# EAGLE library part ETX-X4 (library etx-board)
IDE 1, IDE 2, Ethernet, Miscellaneous ETX Board Connector 100 Pos. Source: www.kontron.com/techlib/whitepapers/etx_spec.pdf
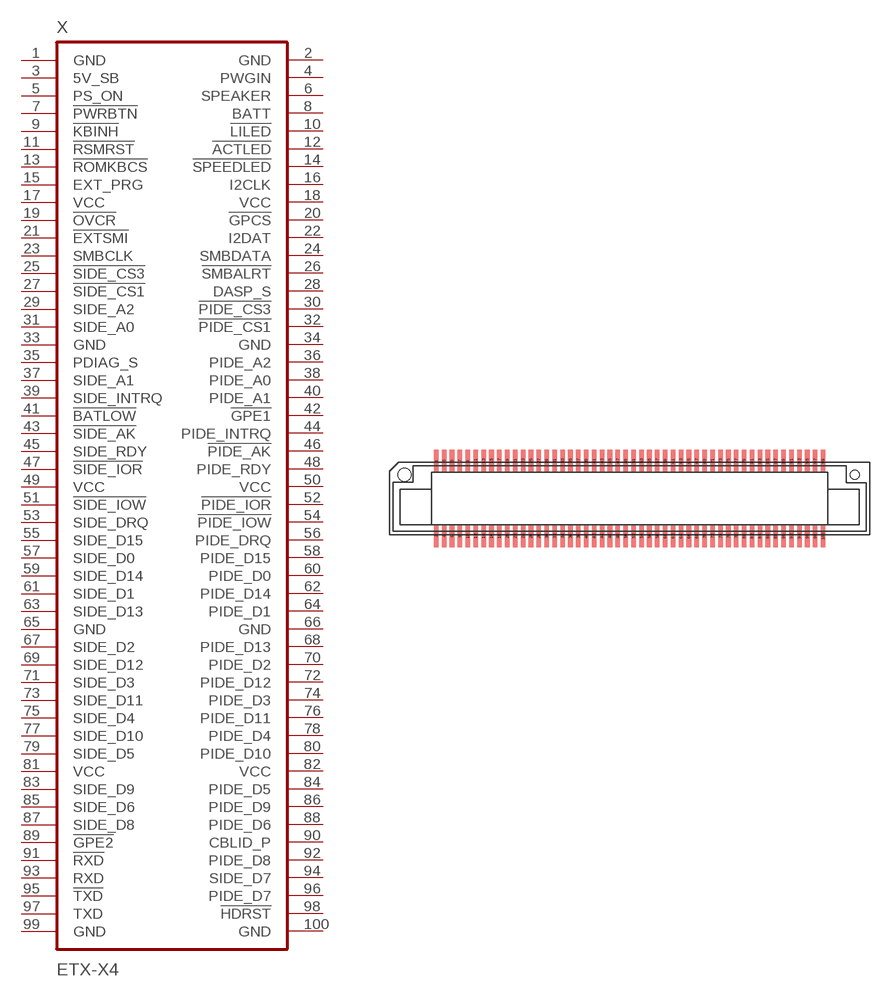
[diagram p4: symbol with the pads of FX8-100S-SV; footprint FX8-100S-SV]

Designator prefix X

## ETX-X4  [FX8-100S-SV]
1  GND  pwr
2  GND  pwr
3  5V_SB
4  PWGIN
5  PS_ON
6  SPEAKER
7  !PWRBTN
8  BATT
9  !KBINH
10  !LILED
11  !RSMRST
12  !ACTLED
13  !ROMKBCS
14  !SPEEDLED
15  EXT_PRG
16  I2CLK
17  VCC  pwr
18  VCC  pwr
19  !OVCR
20  !GPCS
21  !EXTSMI
22  I2DAT
23  SMBCLK
24  SMBDATA
25  !SIDE_CS3
26  !SMBALRT
27  !SIDE_CS1
28  DASP_S
29  SIDE_A2
30  !PIDE_CS3
31  SIDE_A0
32  !PIDE_CS1
33  GND  pwr
34  GND  pwr
35  PDIAG_S
36  PIDE_A2
37  SIDE_A1
38  PIDE_A0
39  SIDE_INTRQ
40  PIDE_A1
41  !BATLOW
42  !GPE1
43  !SIDE_AK
44  PIDE_INTRQ
45  SIDE_RDY
46  !PIDE_AK
47  !SIDE_IOR
48  PIDE_RDY
49  VCC  pwr
50  VCC  pwr
51  !SIDE_IOW
52  !PIDE_IOR
53  SIDE_DRQ
54  !PIDE_IOW
55  SIDE_D15
56  PIDE_DRQ
57  SIDE_D0
58  PIDE_D15
59  SIDE_D14
60  PIDE_D0
61  SIDE_D1
62  PIDE_D14
63  SIDE_D13
64  PIDE_D1
65  GND  pwr
66  GND  pwr
67  SIDE_D2
68  PIDE_D13
69  SIDE_D12
70  PIDE_D2
71  SIDE_D3
72  PIDE_D12
73  SIDE_D11
74  PIDE_D3
75  SIDE_D4
76  PIDE_D11
77  SIDE_D10
78  PIDE_D4
79  SIDE_D5
80  PIDE_D10
81  VCC  pwr
82  VCC  pwr
83  SIDE_D9
84  PIDE_D5
85  SIDE_D6
86  PIDE_D9
87  SIDE_D8
88  PIDE_D6
89  !GPE2
90  CBLID_P
91  !RXD
92  PIDE_D8
93  RXD
94  SIDE_D7
95  !TXD
96  PIDE_D7
97  TXD
98  !HDRST
99  GND  pwr
100  GND  pwr

## Footprint FX8-100S-SV (pad centres in mm)
HIROSE - ETX Board Connector 100 Pos. Source: www.hirose.co.jp/cataloge_hp/e57800016.pdf www.kontron.com/techlib/whitepapers/etx_spec.pdf
smd 0.35 x 1.7: 1 -14.7,2.85; 2 -14.7,-2.85; 3 -14.1,2.85; 4 -14.1,-2.85; 5 -13.5,2.85; 6 -13.5,-2.85; 7 -12.9,2.85; 8 -12.9,-2.85; 9 -12.3,2.85; 10 -12.3,-2.85; 11 -11.7,2.85; 12 -11.7,-2.85; 13 -11.1,2.85; 14 -11.1,-2.85; 15 -10.5,2.85; 16 -10.5,-2.85; 17 -9.9,2.85; 18 -9.9,-2.85; 19 -9.3,2.85; 20 -9.3,-2.85; 21 -8.7,2.85; 22 -8.7,-2.85; 23 -8.1,2.85; 24 -8.1,-2.85; 25 -7.5,2.85; 26 -7.5,-2.85; 27 -6.9,2.85; 28 -6.9,-2.85; 29 -6.3,2.85; 30 -6.3,-2.85; 31 -5.7,2.85; 32 -5.7,-2.85; 33 -5.1,2.85; 34 -5.1,-2.85; 35 -4.5,2.85; 36 -4.5,-2.85; 37 -3.9,2.85; 38 -3.9,-2.85; 39 -3.3,2.85; 40 -3.3,-2.85; 41 -2.7,2.85; 42 -2.7,-2.85; 43 -2.1,2.85; 44 -2.1,-2.85; 45 -1.5,2.85; 46 -1.5,-2.85; 47 -0.9,2.85; 48 -0.9,-2.85; 49 -0.3,2.85; 50 -0.3,-2.85; 51 0.3,2.85; 52 0.3,-2.85; 53 0.9,2.85; 54 0.9,-2.85; 55 1.5,2.85; 56 1.5,-2.85; 57 2.1,2.85; 58 2.1,-2.85; 59 2.7,2.85; 60 2.7,-2.85; 61 3.3,2.85; 62 3.3,-2.85; 63 3.9,2.85; 64 3.9,-2.85; 65 4.5,2.85; 66 4.5,-2.85; 67 5.1,2.85; 68 5.1,-2.85; 69 5.7,2.85; 70 5.7,-2.85; 71 6.3,2.85; 72 6.3,-2.85; 73 6.9,2.85; 74 6.9,-2.85; 75 7.5,2.85; 76 7.5,-2.85; 77 8.1,2.85; 78 8.1,-2.85; 79 8.7,2.85; 80 8.7,-2.85; 81 9.3,2.85; 82 9.3,-2.85; 83 9.9,2.85; 84 9.9,-2.85; 85 10.5,2.85; 86 10.5,-2.85; 87 11.1,2.85; 88 11.1,-2.85; 89 11.7,2.85; 90 11.7,-2.85; 91 12.3,2.85; 92 12.3,-2.85; 93 12.9,2.85; 94 12.9,-2.85; 95 13.5,2.85; 96 13.5,-2.85; 97 14.1,2.85; 98 14.1,-2.85; 99 14.7,2.85; 100 14.7,-2.85
hole 1 at -17.1,1.8
hole 0.7 at 17.1,1.8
